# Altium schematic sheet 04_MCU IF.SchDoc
size 355 x 248 mm
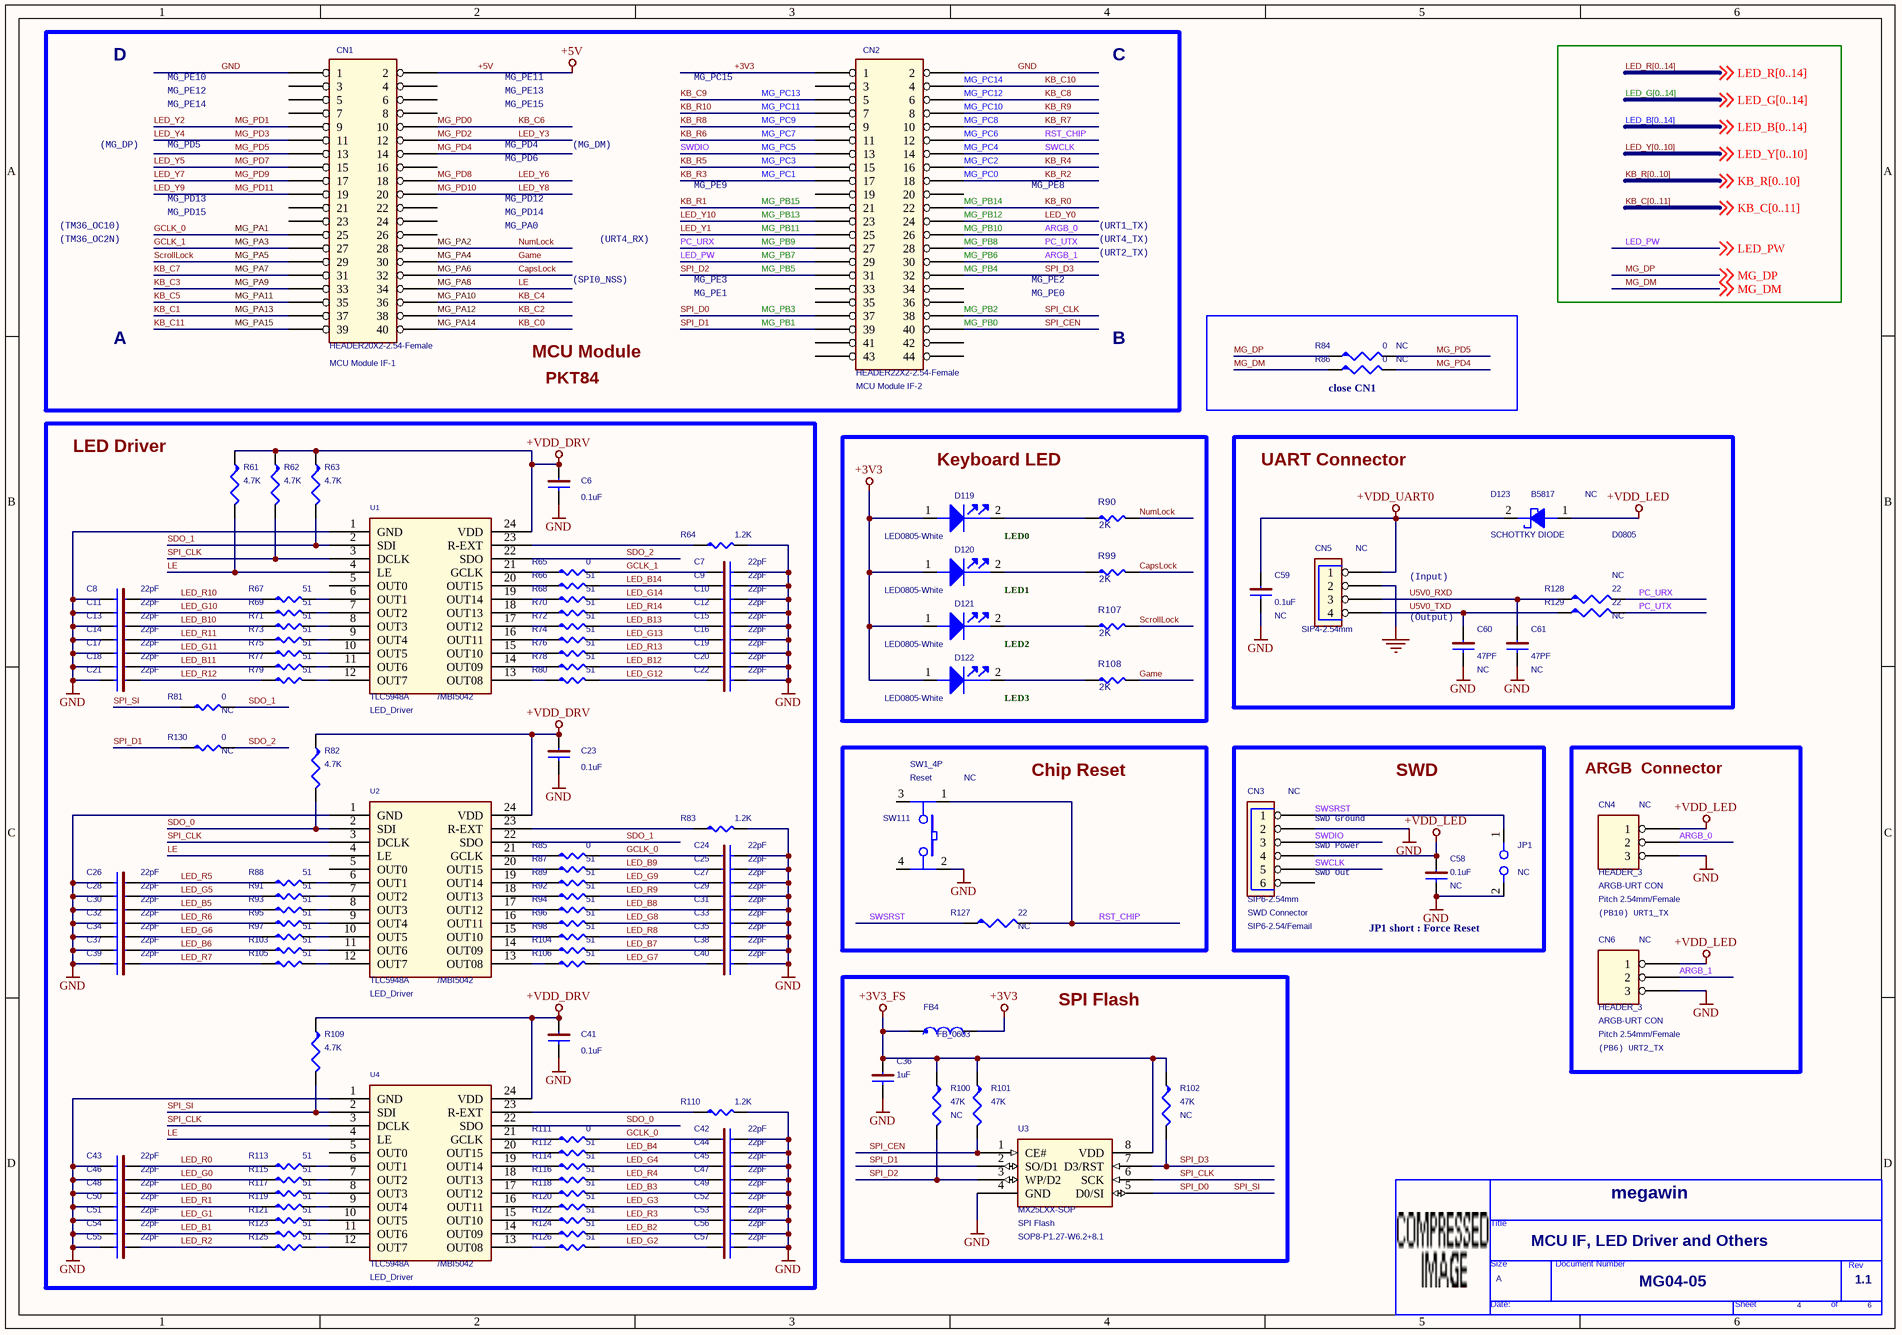
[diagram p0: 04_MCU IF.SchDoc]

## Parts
*  OrgName: megawin  Doc: MG04-05  RevCode: 1.1  Title: MCU IF, LED Driver and Others  Page Size: A  Page Number: 4  Page Count: 6  (hidden comment: TitleBlock_MegaWin)  (graphical)
C6  0.1uF  [C-0603]
C7  22pF  [C-0603]
C8  22pF  [C-0603]
C9  22pF  [C-0603]
C10  22pF  [C-0603]
C11  22pF  [C-0603]
C12  22pF  [C-0603]
C13  22pF  [C-0603]
C14  22pF  [C-0603]
C15  22pF  [C-0603]
C16  22pF  [C-0603]
C17  22pF  [C-0603]
C18  22pF  [C-0603]
C19  22pF  [C-0603]
C20  22pF  [C-0603]
C21  22pF  [C-0603]
C22  22pF  [C-0603]
C23  0.1uF  [C-0603]
C24  22pF  [C-0603]
C25  22pF  [C-0603]
C26  22pF  [C-0603]
C27  22pF  [C-0603]
C28  22pF  [C-0603]
C29  22pF  [C-0603]
C30  22pF  [C-0603]
C31  22pF  [C-0603]
C32  22pF  [C-0603]
C33  22pF  [C-0603]
C34  22pF  [C-0603]
C35  22pF  [C-0603]
C36  1uF  [C-0603]
C37  22pF  [C-0603]
C38  22pF  [C-0603]
C39  22pF  [C-0603]
C40  22pF  [C-0603]
C41  0.1uF  [C-0603]
C42  22pF  [C-0603]
C43  22pF  [C-0603]
C44  22pF  [C-0603]
C45  22pF  [C-0603]
C46  22pF  [C-0603]
C47  22pF  [C-0603]
C48  22pF  [C-0603]
C49  22pF  [C-0603]
C50  22pF  [C-0603]
C51  22pF  [C-0603]
C52  22pF  [C-0603]
C53  22pF  [C-0603]
C54  22pF  [C-0603]
C55  22pF  [C-0603]
C56  22pF  [C-0603]
C57  22pF  [C-0603]
C58  0.1uF  Assembly: NC  [C-0603]
C59  0.1uF  Assembly: NC  [C-0603]
C60  47PF  Assembly: NC  [C-0603]
C61  47PF  Assembly: NC  [C-0603]
CN1  HEADER20X2-2.54-Female  Function: MCU Module IF-1  [HD20X2-P2.54]
CN2  HEADER22X2-2.54-Female  Function: MCU Module IF-2  [HD22X2-P2.54]
CN3  SIP6-2.54mm  Assembly: NC  Function: SWD Connector  Package: SIP6-2.54/Femail  [HD6-P2.54-UL]
CN4  HEADER_3  Function: ARGB-URT CON  Assembly: NC  Package: Pitch 2.54mm/Female  [SIP3-P2.54]
CN5  SIP4-2.54mm  Assembly: NC  [HD4-P2.54-Z12.4X5.7X7-UL]
CN6  HEADER_3  Package: Pitch 2.54mm/Female  Assembly: NC  Function: ARGB-URT CON  [SIP3-P2.54]
D119  LED0805-White  [LED-0805]
D120  LED0805-White  [LED-0805]
D121  LED0805-White  [LED-0805]
D122  LED0805-White  [LED-0805]
D123  B5817  Package: D0805  Function: SCHOTTKY DIODE  Assembly: NC  [D-0805]
FB4  FB_0603  [L-0603]
JP1  Assembly: NC  [SIP2-P2.54]  (hidden comment: JUMPER)
R61  4.7K  [R-0603]
R62  4.7K  [R-0603]
R63  4.7K  [R-0603]
R64  1.2K  [R-0603]
R65  0  [R-0603]
R66  51  [R-0603]
R67  51  [R-0603]
R68  51  [R-0603]
R69  51  [R-0603]
R70  51  [R-0603]
R71  51  [R-0603]
R72  51  [R-0603]
R73  51  [R-0603]
R74  51  [R-0603]
R75  51  [R-0603]
R76  51  [R-0603]
R77  51  [R-0603]
R78  51  [R-0603]
R79  51  [R-0603]
R80  51  [R-0603]
R81  0  Assembly: NC  [R-0603]
R82  4.7K  [R-0603]
R83  1.2K  [R-0603]
R84  0  Assembly: NC  [R-0603]
R85  0  [R-0603]
R86  0  Assembly: NC  [R-0603]
R87  51  [R-0603]
R88  51  [R-0603]
R89  51  [R-0603]
R90  2K  [R-0603]
R91  51  [R-0603]
R92  51  [R-0603]
R93  51  [R-0603]
R94  51  [R-0603]
R95  51  [R-0603]
R96  51  [R-0603]
R97  51  [R-0603]
R98  51  [R-0603]
R99  2K  [R-0603]
R100  47K  Assembly: NC  [R-0603]
R101  47K  [R-0603]
R102  47K  Assembly: NC  [R-0603]
R103  51  [R-0603]
R104  51  [R-0603]
R105  51  [R-0603]
R106  51  [R-0603]
R107  2K  [R-0603]
R108  2K  [R-0603]
R109  4.7K  [R-0603]
R110  1.2K  [R-0603]
R111  0  [R-0603]
R112  51  [R-0603]
R113  51  [R-0603]
R114  51  [R-0603]
R115  51  [R-0603]
R116  51  [R-0603]
R117  51  [R-0603]
R118  51  [R-0603]
R119  51  [R-0603]
R120  51  [R-0603]
R121  51  [R-0603]
R122  51  [R-0603]
R123  51  [R-0603]
R124  51  [R-0603]
R125  51  [R-0603]
R126  51  [R-0603]
R127  22  Assembly: NC  [R-0603]
R128  22  Assembly: NC  [R-0603]
R129  22  Assembly: NC  [R-0603]
R130  0  Assembly: NC  [R-0603]
SW111  SW1_4P  Assembly: NC  Function: Reset  [SW-TACT-P4.5X6.5-Z6.2X6.2X5]
U1  TLC5948A  Alternate: /MBI5042  Function: LED_Driver  [SOP24-P0.65-W6.4-PAD]
U2  TLC5948A  Alternate: /MBI5042  Function: LED_Driver  [SOP24-P0.65-W6.4-PAD]
U3  MX25LXX-SOP  Function: SPI Flash  [SOP8-P1.27-W6.2+8.1]
U4  TLC5948A  Function: LED_Driver  Alternate: /MBI5042  [SOP24-P0.65-W6.4-PAD]

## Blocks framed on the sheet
close CN1: R84 R86
LED Driver: C6-C35 C37-C57 R61-R83 R85 R87-R89 R91-R98 R103-R106 R109-R126 R130 U1 U2 U4
Keyboard LED: D119-D122 R90 R99 R107 R108
UART Connector: C59-C61 CN5 D123 R128 R129
Chip Reset: R127 SW111
SWD: C58 CN3 JP1
ARGB  Connector: CN4 CN6
SPI Flash: C36 FB4 R100-R102 U3

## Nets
+3V3: CN2.1 D119.1(A) D120.1(A) D121.1(A) D122.1(A) FB4.2
+3V3_FS: C36.1 FB4.1 R100.1 R101.1 R102.1 U3.8(VDD)
+5V: CN1.2
+VDD_DRV: C6.1 C23.1 C41.1 R61.1 R62.1 R63.1 R82.1 R109.1 U1.24(VDD) U2.24(VDD) U4.24(VDD)
+VDD_LED: C58.1 CN3.4 CN4.1 CN6.1 D123.1(ANODE)
+VDD_UART0: C59.1 CN5.1 D123.2(CATHODE)
GND: C6.2 C7.2 C8.2 C9.2 C10.2 C11.2 C12.2 C13.2 C14.2 C15.2 C16.2 C17.2 C18.2 C19.2 C20.2 C21.2 C22.2 C23.2 C24.2 C25.2 C26.2 C27.2 C28.2 C29.2 C30.2 C31.2 C32.2 C33.2 C34.2 C35.2 C36.2 C37.2 C38.2 C39.2 C40.2 C41.2 C42.2 C43.2 C44.2 C45.2 C46.2 C47.2 C48.2 C49.2 C50.2 C51.2 C52.2 C53.2 C54.2 C55.2 C56.2 C57.2 C58.2 C59.2 C60.2 C61.2 CN1.1 CN2.2 CN3.2 CN4.3 CN5.2 CN6.3 JP1.2 R64.2 R83.2 R110.2 SW111.2 U1.1(GND) U2.1(GND) U3.4(GND) U4.1(GND)
ARGB_0: CN2.26 CN4.2  [also labelled MG_PB10]
ARGB_1: CN2.30 CN6.2  [also labelled MG_PB6]
CapsLock: CN1.32 R99.2  [also labelled MG_PA6]
Game: CN1.30 R108.2  [also labelled MG_PA4]
GCLK_0: C24.1 C42.1 CN1.25 R85.2 R111.2  [also labelled MG_PA1]
GCLK_1: C7.1 CN1.27 R65.2  [also labelled MG_PA3]
KB_C0: CN1.40  [also labelled MG_PA14]
KB_C1: CN1.37  [also labelled MG_PA13]
KB_C2: CN1.38  [also labelled MG_PA12]
KB_C3: CN1.33  [also labelled MG_PA9]
KB_C4: CN1.36  [also labelled MG_PA10]
KB_C5: CN1.35  [also labelled MG_PA11]
KB_C6: CN1.10  [also labelled MG_PD0]
KB_C7: CN1.31  [also labelled MG_PA7]
KB_C8: CN2.6  [also labelled MG_PC12]
KB_C9: CN2.5  [also labelled MG_PC13]
KB_C10: CN2.4  [also labelled MG_PC14]
KB_C11: CN1.39  [also labelled MG_PA15]
KB_R0: CN2.22  [also labelled MG_PB14]
KB_R1: CN2.21  [also labelled MG_PB15]
KB_R2: CN2.18  [also labelled MG_PC0]
KB_R3: CN2.17  [also labelled MG_PC1]
KB_R4: CN2.16  [also labelled MG_PC2]
KB_R5: CN2.15  [also labelled MG_PC3]
KB_R6: CN2.11  [also labelled MG_PC7]
KB_R7: CN2.10  [also labelled MG_PC8]
KB_R8: CN2.9  [also labelled MG_PC9]
KB_R9: CN2.8  [also labelled MG_PC10]
KB_R10: CN2.7  [also labelled MG_PC11]
LE: CN1.34 R61.2 U1.4(LE) U2.4(LE) U4.4(LE)  [also labelled MG_PA8]
LED_B0: C48.1 R117.1
LED_B1: C54.1 R123.1
LED_B2: C56.1 R124.2
LED_B3: C49.1 R118.2
LED_B4: C44.1 R112.2
LED_B5: C30.1 R93.1
LED_B6: C37.1 R103.1
LED_B7: C38.1 R104.2
LED_B8: C31.1 R94.2
LED_B9: C25.1 R87.2
LED_B10: C13.1 R71.1
LED_B11: C18.1 R77.1
LED_B12: C20.1 R78.2
LED_B13: C15.1 R72.2
LED_B14: C9.1 R66.2
LED_G0: C46.1 R115.1
LED_G1: C51.1 R121.1
LED_G2: C57.1 R126.2
LED_G3: C52.1 R120.2
LED_G4: C45.1 R114.2
LED_G5: C28.1 R91.1
LED_G6: C34.1 R97.1
LED_G7: C40.1 R106.2
LED_G8: C33.1 R96.2
LED_G9: C27.1 R89.2
LED_G10: C11.1 R69.1
LED_G11: C17.1 R75.1
LED_G12: C22.1 R80.2
LED_G13: C16.1 R74.2
LED_G14: C10.1 R68.2
LED_PW: CN2.29 ; off-sheet LED_PW  [also labelled MG_PB7]
LED_R0: C43.1 R113.1
LED_R1: C50.1 R119.1
LED_R2: C55.1 R125.1
LED_R3: C53.1 R122.2
LED_R4: C47.1 R116.2
LED_R5: C26.1 R88.1
LED_R6: C32.1 R95.1
LED_R7: C39.1 R105.1
LED_R8: C35.1 R98.2
LED_R9: C29.1 R92.2
LED_R10: C8.1 R67.1
LED_R11: C14.1 R73.1
LED_R12: C21.1 R79.1
LED_R13: C19.1 R76.2
LED_R14: C12.1 R70.2
LED_Y0: CN2.24  [also labelled MG_PB12]
LED_Y1: CN2.25  [also labelled MG_PB11]
LED_Y2: CN1.9  [also labelled MG_PD1]
LED_Y3: CN1.12  [also labelled MG_PD2]
LED_Y4: CN1.11  [also labelled MG_PD3]
LED_Y5: CN1.15  [also labelled MG_PD7]
LED_Y6: CN1.18  [also labelled MG_PD8]
LED_Y7: CN1.17  [also labelled MG_PD9]
LED_Y8: CN1.20  [also labelled MG_PD10]
LED_Y9: CN1.19  [also labelled MG_PD11]
LED_Y10: CN2.23  [also labelled MG_PB13]
MG_DM: R86.1 ; off-sheet MG_DM
MG_DP: R84.1 ; off-sheet MG_DP
MG_PA2: CN1.28 R90.2  [also labelled NumLock]
MG_PA5: CN1.29 R107.2  [also labelled ScrollLock]
MG_PB0: CN2.40 R101.2 U3.1(CE#)  [also labelled SPI_CEN]
MG_PB1: CN2.39 R130.1 U3.2(SO/D1)  [also labelled SPI_D1]
MG_PB2: CN2.38 R62.2 U1.3(DCLK) U2.3(DCLK) U3.6(SCK) U4.3(DCLK)  [also labelled SPI_CLK]
MG_PB3: CN2.37 R81.1 R109.2 U3.5(D0/SI) U4.2(SDI)  [also labelled SPI_D0, SPI_SI]
MG_PB4: CN2.32 R102.2 U3.7(D3/RST)  [also labelled SPI_D3]
MG_PB5: CN2.31 R100.2 U3.3(WP/D2)  [also labelled SPI_D2]
MG_PB8: CN2.28 R129.2  [also labelled PC_UTX]
MG_PB9: CN2.27 R128.2  [also labelled PC_URX]
MG_PC4: CN2.14 CN3.5  [also labelled SWCLK]
MG_PC5: CN2.13 CN3.3  [also labelled SWDIO]
MG_PC6: CN2.12 R127.2 SW111.1  [also labelled RST_CHIP]
MG_PD4: CN1.14 R86.2
MG_PD5: CN1.13 R84.2
SDO_0: R82.2 U2.2(SDI) U4.22(SDO)
SDO_1: R63.2 R81.2 U1.2(SDI) U2.22(SDO)
SDO_2: R130.2 U1.22(SDO)
SWSRST: CN3.1 JP1.1 R127.1
U5V0_RXD: C61.1 CN5.3 R128.1
U5V0_TXD: C60.1 CN5.4 R129.1
NetD119_2: D119.2(C) R90.1
NetD120_2: D120.2(C) R99.1
NetD121_2: D121.2(C) R107.1
NetD122_2: D122.2(C) R108.1
NetR64_1: R64.1 U1.23(R-EXT)
NetR65_1: R65.1 U1.21(GCLK)
NetR66_1: R66.1 U1.20(OUT15)
NetR67_2: R67.2 U1.6(OUT1)
NetR68_1: R68.1 U1.19(OUT14)
NetR69_2: R69.2 U1.7(OUT2)
NetR70_1: R70.1 U1.18(OUT13)
NetR71_2: R71.2 U1.8(OUT3)
NetR72_1: R72.1 U1.17(OUT12)
NetR73_2: R73.2 U1.9(OUT4)
NetR74_1: R74.1 U1.16(OUT11)
NetR75_2: R75.2 U1.10(OUT5)
NetR76_1: R76.1 U1.15(OUT10)
NetR77_2: R77.2 U1.11(OUT6)
NetR78_1: R78.1 U1.14(OUT09)
NetR79_2: R79.2 U1.12(OUT7)
NetR80_1: R80.1 U1.13(OUT08)
NetR83_1: R83.1 U2.23(R-EXT)
NetR85_1: R85.1 U2.21(GCLK)
NetR87_1: R87.1 U2.20(OUT15)
NetR88_2: R88.2 U2.6(OUT1)
NetR89_1: R89.1 U2.19(OUT14)
NetR91_2: R91.2 U2.7(OUT2)
NetR92_1: R92.1 U2.18(OUT13)
NetR93_2: R93.2 U2.8(OUT3)
NetR94_1: R94.1 U2.17(OUT12)
NetR95_2: R95.2 U2.9(OUT4)
NetR96_1: R96.1 U2.16(OUT11)
NetR97_2: R97.2 U2.10(OUT5)
NetR98_1: R98.1 U2.15(OUT10)
NetR103_2: R103.2 U2.11(OUT6)
NetR104_1: R104.1 U2.14(OUT09)
NetR105_2: R105.2 U2.12(OUT7)
NetR106_1: R106.1 U2.13(OUT08)
NetR110_1: R110.1 U4.23(R-EXT)
NetR111_1: R111.1 U4.21(GCLK)
NetR112_1: R112.1 U4.20(OUT15)
NetR113_2: R113.2 U4.6(OUT1)
NetR114_1: R114.1 U4.19(OUT14)
NetR115_2: R115.2 U4.7(OUT2)
NetR116_1: R116.1 U4.18(OUT13)
NetR117_2: R117.2 U4.8(OUT3)
NetR118_1: R118.1 U4.17(OUT12)
NetR119_2: R119.2 U4.9(OUT4)
NetR120_1: R120.1 U4.16(OUT11)
NetR121_2: R121.2 U4.10(OUT5)
NetR122_1: R122.1 U4.15(OUT10)
NetR123_2: R123.2 U4.11(OUT6)
NetR124_1: R124.1 U4.14(OUT09)
NetR125_2: R125.2 U4.12(OUT7)
NetR126_1: R126.1 U4.13(OUT08)

Not connected (* = marked no-connect by the designer): CN1 3 4 5 6 7 8 16 21 22 23 24 26; CN2 3 19 20 33 34 35 36 41 42 43 44; CN3 6; SW111 3 4; U1 5(OUT0); U2 5(OUT0); U4 5(OUT0)

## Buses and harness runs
bus KB_C[0..11]
bus KB_R[0..10]
bus LED_B[0..14]
bus LED_G[0..14]
bus LED_R[0..14]
bus LED_Y[0..10]

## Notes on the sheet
- D
- C
- MG_PE10
- MG_PE12
- MG_PE14
- MG_PE15
- MG_PE13
- MG_PE11
- MG_PC15
- (MG_DP)
- MG_PD13
- MG_PD5
- MG_PD12
- MG_PD4
- MG_PD6
- (MG_DM)
- MG_PE9
- MG_PE8
- (TM36_OC10)
- (TM36_OC2N)
- MG_PD15
- MG_PD14
- MG_PA0
- (URT4_RX)
- (URT1_TX)
- (URT4_TX)
- (URT2_TX)
- (SPI0_NSS)
- MG_PE3
- MG_PE1
- MG_PE2
- MG_PE0
- A
- MCU Module
- PKT84
- B
- LED0
- LED1
- (Input)
- LED2
- (near C60) (Output)
- (near D122) LED3
- (near CN3) SWD Out
- (near CN3) SWD Power
- (near CN3) SWD Ground
- JP1 short : Force Reset
- (PB10) URT1_TX
- (PB6) URT2_TX

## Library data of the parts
C6-C61 = CAP-NP
CN1 = HEADER20X2
CN2 = HEADER22X2
CN3 = SIP6
CN4 CN6 = HEADER3: 2ND PART FIELD: Pitch 2.54mm
CN5 = SIP4
D119 D120 = LED: CISPartType: Diodes\LED; ATHEROS KEY: 127-00026-000; AtherosDescription: LED, THRU_HOLE,GREEN,3.0MM RADIAL
D121 D122 = LED: CISPartType: Diodes\LED; AtherosDescription: LED, THRU_HOLE,GREEN,3.0MM RADIAL; ATHEROS KEY: 127-00026-000
D123 = DIODE-SCHOTTKY-2
FB4 = FB2
R61-R63 R82 R100-R102 R109 R127-R129 = R
R64-R81 R83 R85 R87-R89 R91-R98 R103-R106 R110-R126 R130 = RES: Opt-Part: _; New PN: R11-0560013; New Description: R,resistor,56ohm/5%/1/10W,0603; CLASS: DISCRETE; Asm Comm: 5010
R84 R86 = R: 2ND PART FIELD: SMD_0805
R90 R99 R107 R108 = R2X: Asm-Lvl: _; Asm Comm: 5010; CLASS: DISCRETE; New Description: R,resistor,56ohm/5%/1/10W,0603; New PN: R11-0560013
SW111 = SW-PB-4P
U1 U2 U4 = IC-TLC5948A
U3 = ICM-25LXX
